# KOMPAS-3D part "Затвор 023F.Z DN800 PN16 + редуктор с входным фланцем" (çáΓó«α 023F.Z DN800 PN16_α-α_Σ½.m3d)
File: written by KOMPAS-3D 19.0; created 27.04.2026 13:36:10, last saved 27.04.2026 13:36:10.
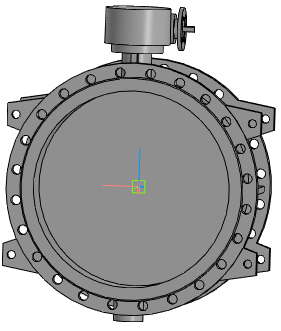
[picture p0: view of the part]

Document properties: Полное имя файла: ..\..\Затвор 023F.Z DN200-DN1600_редуктор с входным фланцем\Затвор 023F.Z DN800 PN16 + редуктор с входным фланцем.a3d

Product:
- Part/product: Затвор 023F.Z DN800 PN16 + редуктор с входным фланцем
    Масса: 790.597

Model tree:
1. Операция без истории:1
